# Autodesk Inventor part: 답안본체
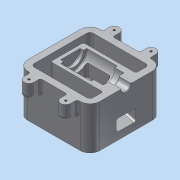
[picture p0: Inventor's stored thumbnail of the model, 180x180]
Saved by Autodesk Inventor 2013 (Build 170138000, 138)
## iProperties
Created: 2018-01
Part Number: 답안본체
Material: 알루미늄 6061
Document SubType Name: Modeling
Designer: dgall
Density: 2.71 g/cm^3
Mass: 998.576 g
Surface Area: 832.368 cm^2
Volume: 368.478 cm^3
Author: dgall
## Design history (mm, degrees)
sketch "스케치1"
  geometry: L1 (-55, 55)-(55, 55); L2 (55, 55)-(55, -55); L3 (55, -55)-(-55, -55); L4 (-55, -55)-(-55, 55); 3 further points
  constraints: 8 end point, 2 midpoint, 2 perpendicular, 1 horizontal, 1 horizontal alignment, 1 parallel, 1 vertical alignment
  dimensions: "d0" = 110 distance of L1.start L1.end; "d2" = 110 distance of L1.end L2.end
extrude "돌출1" new body sketch "스케치1" distance "d3" = 65; taper "d4" = 0 deg
fillet "모깎기1" dims "d5" = 15
sketch "스케치2"
  geometry: L1 (55, 65)-(55, 0) reference; L2 (55, 0)-(-55, 0) reference; L3 (-55, 0)-(-55, 65) reference; L4 (-55, 65)-(55, 65) reference; 1 further point
  node "절단 모서리 투영1"
sketch "스케치3"
  geometry: L1 (55, 65)-(55, 0) reference; L2 (55, 0)-(-55, 0) reference; L3 (-55, 0)-(-55, 65) reference; L4 (-55, 65)-(55, 65) reference; L5 (-55, 65)-(55, 65); L6 (-55, 65)-(-55, 57.5); L7 (-55, 57.5)-(-36, 57.5); L8 (-36, 57.5)-(-36, 49); L9 (-36, 49)-(-22, 49); L10 (-22, 49)-(-22, 45); L11 (-22, 45)-(25, 45); L12 (25, 45)-(25, 50); L13 (25, 50)-(30, 50); L14 (30, 50)-(30, 65); 1 further point
  constraints: 20 end point, 5 parallel, 3 perpendicular, 2 point on line, 1 collinear
  dimensions: "d7" = 19 distance of L6.end L7.end; "d9" = 15 diameter of L7 L4; "d10" = 32 diameter of L9 L4; "d11" = 40 diameter of L11 L4; "d13" = 30 diameter of L13 L4; "d14" = 14 distance of L8.end L9.end; "d15" = 47 distance of L10.end L11.end; "d16" = 5 distance of L12.end L13.end
revolve "회전1" sketch "스케치3" stored, may be unused: angle "d17" = 90 deg
sketch "스케치4"
  geometry: L1 (55, 65)-(55, 0) reference; L2 (55, 0)-(-55, 0) reference; L3 (-55, 0)-(-55, 57.5) reference; L4 (-55, 57.5)-(-36, 57.5) reference; L5 (-36, 57.5)-(-36, 49) reference; L6 (-36, 49)-(-22, 49) reference; L7 (-22, 49)-(-22, 45) reference; L8 (-22, 45)-(25, 45) reference; L9 (25, 45)-(25, 50) reference; L10 (25, 50)-(30, 50) reference; L11 (30, 50)-(30, 65) reference; L12 (30, 65)-(55, 65) reference; L13 (-55, 29.061)-(-17, 39.243); L14 (-17, 39.243)-(-17, 45); L15 (-55, 11.061)-(20, 31.157); L16 (20, 31.157)-(20, 45); L17 (-45, 0)-(-45, 8.564); L18 (-45, 8.564)-(35, 30); L19 (35, 30)-(35, 65); L20 (45, 65)-(45, 0); L21 (-17, 45)-(-17, 65); L22 (20, 45)-(20, 65); L23 (20, 65)-(17.646, 65); L24 (17.646, 65)-(-17, 65); 1 further point
  constraints: 24 end point, 8 point on line, 6 parallel, 4 perpendicular, 3 vertical alignment, 1 horizontal alignment
  dimensions: "d19" = 18 distance of L15.start L13.start; "d21" = 37 horizontal distance of L16.end L13.end; "d22" = 75 deg angle of L13 L3; "d23" = 5 distance of L7.end L14.end; "d25" = 30 distance from line of L2 L18.end; "d26" = 10 distance between parallel lines of L20 L19; "d27" = 20 distance between parallel lines of L1 L19; "d28" = 5 distance between parallel lines of L15 L18; "d29" = 10 distance between parallel lines of L3 L17; "d32" = 20 distance of L14.end L21.end; "d34" = 20 distance of L16.end L22.end
  node "절단 모서리 투영3"
extrude "돌출2" cut sketch "스케치4" stored distance "d30" = 90; taper "d31" = 0 deg
extrude "돌출3" join sketch "스케치4" stored distance "d35" = 30; taper "d36" = 0 deg
sketch "스케치5"
  geometry: L1 (-35, 45)-(-35, -45) reference; L2 (55, 7.5)-(55, 40) reference; L3 (40, 55)-(-40, 55) reference; L4 (-40, -55)-(40, -55) reference; L5 (55, -40)-(55, -7.5) reference; L6 (36, 16)-(36, 7.5) reference; L7 (-35, -45)-(45, -45); L8 (45, -45)-(45, -25); L9 (45, -25)-(-35, -25); L10 (-35, 25)-(45, 25); L11 (45, 25)-(45, 45); L12 (45, 45)-(-35, 45); 1 further point
  constraints: 12 end point, 5 perpendicular, 2 point on line, 1 parallel
  dimensions: "d37" = 30 distance between parallel lines of L9 L4; "d39" = 30 distance between parallel lines of L10 L3; "d40" = 10 distance between parallel lines of L8 L5; "d41" = 10 distance between parallel lines of L2 L11
extrude "돌출4" cut sketch "스케치5" stored distance "d42" = 30; taper "d43" = 0 deg
fillet "모깎기2" dims "d44" = 5
fillet "모깎기3" dims "d45" = 3
fillet "모깎기4" dims "d46" = 3
sketch "스케치6"
  geometry: L1 (55, 7.5)-(55, 40) reference; L2 (40, 55)-(-40, 55) reference; L3 (-55, 40)-(-55, -40) reference; L4 (-40, -55)-(40, -55) reference; L5 (36, 16)-(36, 7.5) reference; L6 (35.5, -55)-(35.5, -65); L7 (20.5, -65)-(20.5, -55); L8 (-35.5, -55)-(-35.5, -65); L9 (-20.5, -65)-(-20.5, -55); L10 (20.5, 55)-(20.5, 65); L11 (35.5, 65)-(35.5, 55); L12 (-35.5, 55)-(-35.5, 65); L13 (-20.5, 65)-(-20.5, 55); A1 r 7.5 centre (28, -65) between (20.5, -65) and (35.5, -65); A2 r 7.5 centre (-28, -65) between (-35.5, -65) and (-20.5, -65); A3 r 7.5 centre (28, 65) between (35.5, 65) and (20.5, 65); A4 r 7.5 centre (-28, 65) between (-20.5, 65) and (-35.5, 65); 2 further points
  constraints: 16 end point, 8 point on circle, 8 point on line, 8 tangent, 5 perpendicular, 4 centre point, 3 parallel, 1 equal radius
  dimensions: "d47" = 27 horizontal distance of point (55, -40) A1.centre; "d48" = 7.5 radius of A1; "d49" = 10 distance from line of L4 A1.centre; "d50" = 56 distance of A1.centre A2.centre; "d51" = 27 horizontal distance of L3.end A2.centre; "d52" = 7.5 radius of A2; "d56" = 27 distance from line of A3.centre L1; "d60" = 7.5 radius of A4; "d61" = 56 distance of A3.centre A4.centre; "d62" = 27 distance from line of L3 A4.centre; "d63" = 10 distance from line of L2 A4.centre
extrude "돌출5" join sketch "스케치6" distance "d64" = 20; taper "d65" = 0 deg
hole "구멍1" diameter "d68" = 3.242; stored, may be unused: countersink angle "d72" = 90 deg, drill point angle "d74" = 120 deg; dims "d66" = 10, "d67" = 10, "d69" = 9, "d70" = 4, "d71" = 2, "d73" = 11
hole "구멍2" diameter "d80" = 3.242; stored, may be unused: countersink angle "d84" = 90 deg, drill point angle "d86" = 120 deg; dims "d78" = 10, "d79" = 10, "d81" = 9, "d82" = 4, "d83" = 2, "d85" = 11
fillet "모깎기5" dims "d90" = 1
chamfer "모따기1" distance "d91" = 1; stored, may be unused: second distance "d92" = 2, angle "d93" = 45 deg
fillet "모깎기6" dims "d94" = 3
fillet "모깎기7" dims "d95" = 3
fillet "모깎기8" dims "d96" = 3
extrude "돌출6" cut sketch "스케치4" stored distance "d97" = 30; taper "d98" = 0 deg
fillet "모깎기9" dims "d99" = 3
fillet "모깎기13" dims "d103" = 3
fillet "모깎기14" dims "d104" = 3
sketch "스케치7"
  geometry: L1 (0, 0)-(80, 0) reference; 3 further points
  constraints: 1 midpoint, 1 vertical alignment, 1 other
  dimensions: "d106" = 20 distance from line of L1 point (40, -20)
feature "엠보싱1" sketch "스케치7" dims "d0" = 110, "d2" = 110, "d7" = 19, "d9" = 15, "d10" = 32, "d11" = 40, "d13" = 30, "d14" = 14, "d15" = 47, "d16" = 5, "d107" = 0.5, "d108" = 0
node "솔리드1"
pattern_linear "직사각형 패턴1" dims "d77" = 56
pattern_linear "직사각형 패턴2" dims "d89" = 56
node "절단 모서리 투영2"
